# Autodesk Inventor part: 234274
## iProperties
Created: 2006-07
Part Number: 234274
Material: 45H vz
Description: Gewindestift
Vendor: Autodesk Inc.
Document SubType Name: Modeling
Standard: DIN 914
Designer: I.Baliuc
Standards Organization: DIN
Language: de-DE
Size Designation: M5 x 10
Categories: <MemberInstance Version="R10.0.0"><Categories><Category DisplayName="Schrauben" InternalName="e4da775c-781d-43d5-af7c-5136215cf5a6" Mnemonic="FSTN"><Category Di
Density: 7.86 g/cm^3
Mass: 1.13067 g
Surface Area: 1.87837 cm^2
Volume: 0.143851 cm^3
Abmessung: M5 x 10
Author: T.Messerschmitt
Comments: DIN 914 - M5 x 10
Revision Number: 234274
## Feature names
1. Körper [Revolution]
2. Loch [Extrusion]
3. Fase1 [Chamfer]
4. Fase2 [Chamfer]
